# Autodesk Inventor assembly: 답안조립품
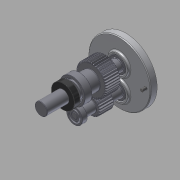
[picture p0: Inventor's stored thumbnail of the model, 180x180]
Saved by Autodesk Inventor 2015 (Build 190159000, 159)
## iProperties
Created: 2016-02
Part Number: 답안조립품
Document SubType Name: Assembly
Designer: Administrator
Mass: 1590.77 g
Surface Area: 1269.69 cm^2
Volume: 451.725 cm^3
Density: 3.52155 g/cm^3
Author: Administrator
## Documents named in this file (10)
- C:\Users\Administrator\Desktop\460209V1014\답안조립품.iam
- C:\Users\Administrator\Desktop\460209V1014\본체.ipt
- C:\Users\Administrator\Desktop\460209V1014\커버.ipt
- C:\Users\Administrator\Desktop\460209V1014\볼트 M4 x 10.ipt
- C:\Users\Administrator\Desktop\460209V1014\오일실 8 22 7.ipt
- C:\Users\Administrator\Desktop\460209V1014\베어링 608.ipt
- C:\Users\Administrator\Desktop\460209V1014\메인축.ipt
- C:\Users\Administrator\Desktop\460209V1014\서브축.ipt
- C:\Users\Administrator\Desktop\460209V1014\오일실 17 32 8.ipt
- C:\Users\Administrator\Desktop\460209V1014\베어링 6003.ipt
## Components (2 placed, 1 different names)
1. ISO 4762 M4 x 10:1 — Insert:2
2. ISO 4762 M4 x 10:2 — Insert:1
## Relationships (2: Insert 2)
- Insert:1: ISO 4762 M4 x 10:2
- Insert:2: ISO 4762 M4 x 10:1
